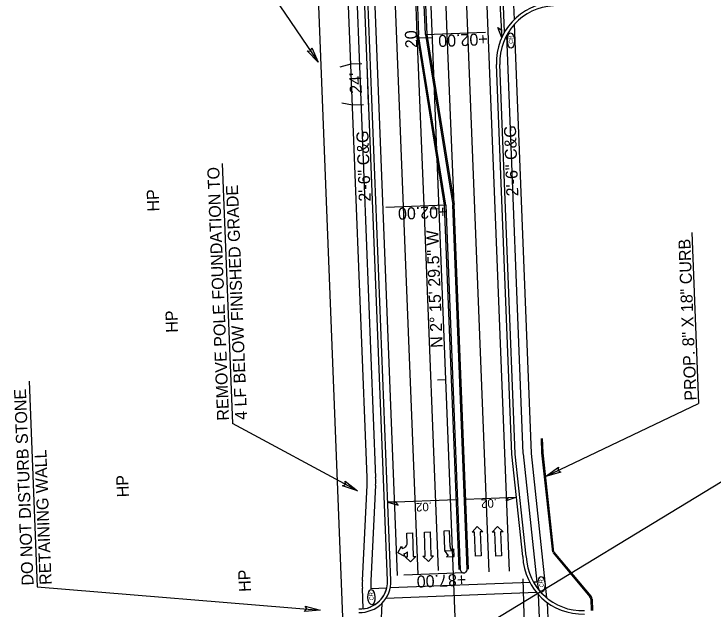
# Model space of a CAD drawing. Extents: x 1627861 to 1629601, y 761281 to 766239.
# Drawn here: x 1628227.2 to 1628635.3, y 762141.5 to 762489 of the extents above; entities that cross this region are included whole.
import ezdxf

# ---------------------------------------------------------------- set-up
doc = ezdxf.new("R2010")
doc.units = 0
for name, color, linetype in [('Cogo Default Point CELL', 7, 'Continuous'), ('Exist Other Culture Sign Leader', 7, 'Continuous'), ('Exist Property Tie Line Leader', 7, 'Continuous'), ('Exist Property Tie Line Text', 7, 'Continuous'), ('Exist Right of Way Line Leader', 7, 'Continuous'), ('Exist Right of Way Monument Leader', 7, 'Continuous'), ('Exist Right of Way Monument Text', 7, 'Continuous'), ('Exist Utilities Gas Meter CELL', 7, 'Continuous'), ('Exist Utilities Gas Meter Cogo Elevation', 7, 'Continuous'), ('Exist Utilities Gas Meter Cogo Number', 7, 'Continuous'), ('Exist Utilities Gas UG Line', 7, 'Continuous'), ('Exist Utilities Other Unknown UG SUE Text', 7, 'Continuous'), ('Exist Utilities Power UG Cable SUE LOS B Cogo Point CELL', 7, 'Continuous'), ('Exist Utilities Telephone UG Cable SUE LOS B Cogo Comment', 7, 'Continuous'), ('Exist Utilities Telephone UG Cable SUE LOS B Cogo Number', 7, 'Continuous'), ('Exist Utilities Water Fire Hydrant Cogo Elevation', 7, 'Continuous'), ('Exist Utilities Water Fire Hydrant Cogo Number', 7, 'Continuous'), ('Exist Utilities Water Meter Cogo Elevation', 7, 'Continuous'), ('Exist Utilities Water UG Line SUE LOS B Cogo Number', 7, 'Continuous'), ('Exist Utilities Water Valve CELL', 7, 'Continuous'), ('Scratch_Level_0', 7, 'Continuous'), ('Scratch_Level_1', 7, 'Continuous'), ('Typical Terminator CELL', 7, 'Continuous')]:
    doc.layers.add(name, color=color, linetype=linetype)

msp = doc.modelspace()

# ---------------------------------------------------------------- linework, layer by layer
at = {"layer": 'Exist Property Tie Line Text'}
for p, q in [((1628475.45, 762375.23), (1628470.46, 762375.03)), ((1628479.39, 762275.31), (1628474.4, 762275.11)), ((1628483.33, 762175.39), (1628478.34, 762175.19))]:
    msp.add_line(p, q, dxfattribs=at)
at = {"layer": 'Exist Right of Way Line Leader'}
msp.add_line((1628486.68, 762122.66), (1628711.64, 762259.34), dxfattribs=at)
at = {"layer": 'Exist Right of Way Monument Leader'}
for p, q in [((1628494.64, 762186.35), (1628497.62, 762189.61)), ((1628497.62, 762189.61), (1628500.94, 762186.58)), ((1628506.44, 762186.35), (1628509.43, 762189.61)), ((1628509.43, 762189.61), (1628512.74, 762186.57)), ((1628456.52, 762185.8), (1628459.81, 762185.92)), ((1628456.75, 762179.35), (1628456.52, 762185.8)), ((1628459.81, 762185.92), (1628460.31, 762172.13)), ((1628466.82, 762186.37), (1628470.12, 762186.49)), ((1628467.32, 762172.38), (1628466.82, 762186.37)), ((1628470.12, 762186.49), (1628470.62, 762172.5)), ((1628481.48, 762187.15), (1628478.18, 762187.03)), ((1628478.18, 762187.03), (1628478.56, 762176.49)), ((1628481.81, 762178.01), (1628481.48, 762187.15)), ((1628496.14, 762186.41), (1628494.64, 762186.35)), ((1628496.64, 762172.42), (1628496.14, 762186.41)), ((1628500.94, 762186.58), (1628499.44, 762186.53)), ((1628499.44, 762186.53), (1628499.94, 762172.54)), ((1628507.94, 762186.4), (1628506.44, 762186.35)), ((1628508.45, 762172.41), (1628507.94, 762186.4)), ((1628512.74, 762186.57), (1628511.24, 762186.52)), ((1628511.24, 762186.52), (1628511.74, 762172.53)), ((1628451.38, 762174.31), (1628453.44, 762178.23)), ((1628453.44, 762178.23), (1628453.89, 762176.85)), ((1628484.06, 762176.64), (1628483.04, 762175.55)), ((1628484.17, 762172.14), (1628484.06, 762176.64)), ((1628455.3, 762172.25), (1628451.38, 762174.31)), ((1628454.85, 762173.68), (1628455.3, 762172.25)), ((1628457.01, 762172.01), (1628456.91, 762174.86)), ((1628461.81, 762172.18), (1628458.77, 762168.97)), ((1628460.31, 762172.13), (1628461.81, 762172.18)), ((1628465.82, 762172.33), (1628467.32, 762172.38)), ((1628469.13, 762169.29), (1628465.82, 762172.33)), ((1628472.12, 762172.55), (1628469.13, 762169.29)), ((1628470.62, 762172.5), (1628472.12, 762172.55)), ((1628480.78, 762173.12), (1628479.77, 762172.03)), ((1628479.77, 762172.03), (1628484.17, 762172.14)), ((1628499.94, 762172.54), (1628496.64, 762172.42)), ((1628511.74, 762172.53), (1628508.45, 762172.41)), ((1628455.51, 762171.95), (1628457.01, 762172.01)), ((1628458.77, 762168.97), (1628455.51, 762171.95))]:
    msp.add_line(p, q, dxfattribs=at)
for centre, radius, start, end in [((1628452.83, 762181.16), 4.43, 283.7683, 314.6218), ((1628454.28, 762179.91), 2.52, 311.1317, 347.4437), ((1628483.7, 762177.47), 5.25, 190.7347, 236.0464), ((1628485.06, 762178.11), 3.28, 182.0586, 231.7168), ((1628453.8, 762178), 4.43, 283.6494, 314.528)]:
    msp.add_arc(centre, radius, start, end, dxfattribs=at)
at = {"layer": 'Exist Right of Way Monument Text'}
for p, q in [((1628447.23, 762158.21), (1628426.86, 762674.72)), ((1628423.84, 762459.7), (1628417.52, 762457.91)), ((1628517.88, 762231.98), (1628508.91, 762459.47)), ((1628424.78, 762435.72), (1628418.54, 762436.94)), ((1628524.24, 762172.14), (1628517.88, 762231.98))]:
    msp.add_line(p, q, dxfattribs=at)
for centre, radius, start, end in [((1628543.88, 762460.85), 35, 92.9208, 182.2582), ((1628559.22, 762173.52), 35, 182.2582, 271.7963), ((1628429.25, 762157.5), 18, 267.7354, 2.2582)]:
    msp.add_arc(centre, radius, start, end, dxfattribs=at)
at = {"layer": 'Exist Utilities Gas Meter CELL'}
msp.add_line((1628486.22, 762102.11), (1628373.12, 764970.45), dxfattribs=at)
at = {"layer": 'Exist Utilities Gas Meter Cogo Elevation'}
for p, q in [((1628445.23, 762158.13), (1628424.87, 762674.64)), ((1628519.88, 762232.06), (1628510.91, 762459.56)), ((1628526.23, 762172.35), (1628519.89, 762232.01))]:
    msp.add_line(p, q, dxfattribs=at)
for centre, radius, start, end in [((1628543.88, 762460.85), 33, 92.9208, 182.2582), ((1628559.22, 762173.52), 33, 182.2582, 271.7963), ((1628429.25, 762157.5), 16, 267.7354, 2.2582)]:
    msp.add_arc(centre, radius, start, end, dxfattribs=at)
at = {"layer": 'Exist Utilities Gas Meter Cogo Number'}
for points in [[(1628401.04, 762469.15), (1628404.83, 762460.84), (1628398.41, 762467.42), (1628400.38, 762467.37)], [(1628546.4, 762221.43), (1628537.61, 762218.95), (1628545.09, 762224.29), (1628544.74, 762222.35)], [(1628420.61, 762216.11), (1628427.8, 762210.48), (1628419.07, 762213.36), (1628420.84, 762214.23)], [(1628397.22, 762143.18), (1628406.06, 762140.89), (1628396.91, 762140.04), (1628398.19, 762141.54)]]:
    msp.add_lwpolyline(points, close=True, dxfattribs=at)
at = {"layer": 'Exist Utilities Gas UG Line'}
for p, q in [((1628504.58, 762163.21), (1628465.73, 763148.45)), ((1628516.57, 762163.69), (1628477.72, 763148.92)), ((1628451.12, 762161.11), (1628412.27, 763146.34)), ((1628463.11, 762161.58), (1628424.26, 763146.81)), ((1628480.18, 762477.5), (1628471.51, 762697.33)), ((1628462.69, 762476.81), (1628454.26, 762690.64)), ((1628461.88, 762636.9), (1628468.19, 762477.02)), ((1628466.63, 762376.88), (1628462.69, 762476.81)), ((1628478.63, 762377.27), (1628462.7, 762476.72)), ((1628468.18, 762477.11), (1628484.11, 762377.66)), ((1628484.12, 762377.57), (1628480.18, 762477.5)), ((1628475.02, 762164.03), (1628466.63, 762376.88)), ((1628487.02, 762164.51), (1628478.62, 762377.36)), ((1628492.51, 762164.72), (1628484.12, 762377.57))]:
    msp.add_line(p, q, dxfattribs=at)
at = {"layer": 'Exist Utilities Other Unknown UG SUE Text'}
for p, q in [((1628455.01, 762690.67), (1628463.44, 762476.84)), ((1628467.44, 762476.99), (1628461.13, 762636.87)), ((1628479.37, 762377.39), (1628463.44, 762476.84)), ((1628467.44, 762476.99), (1628483.37, 762377.54)), ((1628479.37, 762377.39), (1628487.76, 762164.55)), ((1628491.76, 762164.71), (1628483.37, 762377.54))]:
    msp.add_line(p, q, dxfattribs=at)
msp.add_arc((1628489.76, 762164.63), 2, 182.2582, 2.2582, dxfattribs=at)
at = {"layer": 'Exist Utilities Telephone UG Cable SUE LOS B Cogo Comment'}
for p, q in [((1628513.66, 762478.51), (1628511.35, 762537.26)), ((1628519.38, 762485.84), (1628517.59, 762531.2)), ((1628528.34, 762157.03), (1628446.87, 762153.82)), ((1628532.27, 762151.18), (1628444.35, 762147.71)), ((1628533.3, 762150), (1628535.3, 762099.17)), ((1628538.49, 762145.32), (1628540.16, 762102.92))]:
    msp.add_line(p, q, dxfattribs=at)
at = {"layer": 'Exist Utilities Telephone UG Cable SUE LOS B Cogo Number'}
for p, q in [((1628535.45, 762232.68), (1628535.12, 762241.01)), ((1628536.12, 762232.7), (1628535.79, 762241.04)), ((1628541.74, 762174.64), (1628535.45, 762232.63)), ((1628542.41, 762174.71), (1628536.12, 762232.7)), ((1628541.9, 762174.28), (1628563.47, 762148.63)), ((1628542.41, 762174.71), (1628563.99, 762149.05)), ((1628564.03, 762147.19), (1628564.23, 762140.66)), ((1628564.69, 762147.22), (1628564.9, 762140.68))]:
    msp.add_line(p, q, dxfattribs=at)
for radius in [2.33, 3]:
    msp.add_arc((1628561.7, 762147.12), radius, 1.7963, 40.0697, dxfattribs=at)
at = {"layer": 'Exist Utilities Water Fire Hydrant Cogo Elevation'}
for centre in [(1628517.32, 762473.46), (1628535.18, 762155.99), (1628435.9, 762148.4)]:
    msp.add_ellipse(centre, major_axis=(-0.18, 4.48), ratio=0.462467, dxfattribs=at)
at = {"layer": 'Exist Utilities Water Fire Hydrant Cogo Number'}
msp.add_line((1628420.61, 762102.01), (1628396.89, 762704.96), dxfattribs=at)
at = {"layer": 'Exist Utilities Water Meter Cogo Elevation'}
msp.add_line((1628471.51, 762475.15), (1628463.52, 762474.84), dxfattribs=at)
at = {"layer": 'Exist Utilities Water UG Line SUE LOS B Cogo Number'}
for p, q in [((1628508.54, 762541.66), (1628511.94, 762475.15)), ((1628445.43, 762203.9), (1628485.4, 762205.48)), ((1628490.9, 762205.7), (1628520.55, 762206.87)), ((1628524.3, 762159.05), (1628526.58, 762086.51)), ((1628440.3, 762097.42), (1628442.18, 762144.99))]:
    msp.add_line(p, q, dxfattribs=at)
at = {"layer": 'Exist Utilities Water Valve CELL'}
for p, q in [((1628433.36, 762218.24), (1628415.37, 762674.25)), ((1628420.37, 762674.47), (1628438.36, 762218.21)), ((1628529.37, 762232.44), (1628519.49, 762483.08)), ((1628514.75, 762476.36), (1628524.38, 762232.24)), ((1628524.4, 762232.19), (1628532.37, 762157.19)), ((1628538.38, 762147.93), (1628529.4, 762232.39)), ((1628430.62, 762158.07), (1628433.34, 762213.84)), ((1628438.34, 762213.81), (1628435.63, 762158.05)), ((1628532.37, 762157.19), (1628530.58, 762157.12)), ((1628431.08, 762141.61), (1628430.6, 762153.67)), ((1628435.61, 762153.65), (1628435.62, 762153.38)), ((1628444.8, 762153.74), (1628435.62, 762153.38))]:
    msp.add_line(p, q, dxfattribs=at)
for centre, radius, start, end in [((1628383.4, 762216.27), 50, 357.2125, 2.2582), ((1628388.4, 762216.24), 50, 357.2125, 2.2582), ((1628480.56, 762155.64), 50, 177.2125, 182.2582), ((1628485.57, 762155.62), 50, 177.2125, 182.2582), ((1628559.22, 762173.52), 33, 209.7952, 230.8524), ((1628429.25, 762157.5), 16, 276.5683, 346.3887)]:
    msp.add_arc(centre, radius, start, end, dxfattribs=at)
at = {"layer": 'Scratch_Level_0'}
for p, q in [((1628364.02, 762520.77), (1628404.83, 762460.84)), ((1628467.44, 762476.99), (1628502.41, 762478.37)), ((1628434.27, 762436.09), (1628433.33, 762460.08)), ((1628348.81, 762401.75), (1628354.81, 762249.78)), ((1628479.37, 762377.39), (1628444.4, 762376.01)), ((1628622.89, 762361.42), (1628626.83, 762261.56)), ((1628236.02, 762274.54), (1628240.75, 762154.52)), ((1628537.61, 762218.95), (1628626.83, 762261.56)), ((1628427.8, 762210.48), (1628354.81, 762249.78)), ((1628489.84, 762162.63), (1628454.87, 762161.25)), ((1628240.75, 762154.52), (1628406.06, 762140.89))]:
    msp.add_line(p, q, dxfattribs=at)
at = {"layer": 'Scratch_Level_1'}
for p, q in [((1628430.33, 762459.96), (1628423.84, 762459.7)), ((1628431.28, 762435.98), (1628424.78, 762435.72))]:
    msp.add_line(p, q, dxfattribs=at)
at = {"layer": 'Typical Terminator CELL'}
for points in [[(1628511.94, 762475.15), (1628509.63, 762481.04), (1628511.7, 762479.76)], [(1628520.55, 762206.87), (1628514.63, 762204.63), (1628515.93, 762206.68)], [(1628445.43, 762203.9), (1628451.5, 762202.13), (1628450.05, 762204.07)]]:
    msp.add_lwpolyline(points, close=True, dxfattribs=at)

# ---------------------------------------------------------------- texts
at = {"layer": 'Cogo Default Point CELL'}
msp.add_text('N 2%%d 15\' 29.5" W', height=7, rotation=92.2582, dxfattribs=at).set_placement((1628477.55, 762294.17))
at = {"layer": 'Exist Other Culture Sign Leader'}
for s, p in [('HP', (1628312.12, 762373.77)), ('PROP. 8" X 18" CURB', (1628625.76, 762263.35)), ('HP', (1628323.05, 762303.01)), ('HP', (1628294.35, 762206.89)), ('HP', (1628365.55, 762151.66))]:
    msp.add_text(s, height=7, rotation=92.2582, dxfattribs=at).set_placement(p)
at = {"layer": 'Exist Property Tie Line Leader'}
msp.add_text('20', height=7, rotation=92.2582, dxfattribs=at).set_placement((1628462.74, 762469.18))
at = {"layer": 'Exist Utilities Power UG Cable SUE LOS B Cogo Point CELL'}
for s, p in [('REMOVE POLE FOUNDATION TO', (1628352.83, 762251.66)), ('4 LF BELOW FINISHED GRADE', (1628363.32, 762252.08)), ('DO NOT DISTURB STONE', (1628238.71, 762155.34)), ('RETAINING WALL', (1628249.2, 762155.75))]:
    msp.add_text(s, height=7, rotation=92.2582, dxfattribs=at).set_placement(p)
at = {"layer": 'Exist Utilities Water Fire Hydrant Cogo Elevation'}
for p in [(1628518.57, 762471.62), (1628536.43, 762154.16), (1628437.16, 762146.56)]:
    msp.add_text('CR', height=2.4, rotation=92.2582, dxfattribs=at).set_placement(p)
at = {"layer": 'Exist Utilities Water UG Line SUE LOS B Cogo Number'}
for rotation, p in [(182.2582, (1628509.08, 762205.82)), (182.0961, (1628471.13, 762203.74))]:
    msp.add_text('.02', height=5, rotation=rotation, dxfattribs=at).set_placement(p)
at = {"layer": 'Scratch_Level_0'}
for s, rotation, p in [('+02.00', 182.2582, (1628503.64, 762477.82)), ("24'", 92.2582, (1628430.35, 762442.62)), ('2\'-6" C&G', 92.0586, (1628521.7, 762382.64)), ('2\'-6" C&G', 92.0586, (1628435.54, 762379.55)), ('+02.00', 182.2582, (1628480.13, 762376.94)), ('+87.00', 182.2582, (1628491.07, 762162.08))]:
    msp.add_text(s, height=7, rotation=rotation, dxfattribs=at).set_placement(p)

doc.saveas('drawing.dxf')
